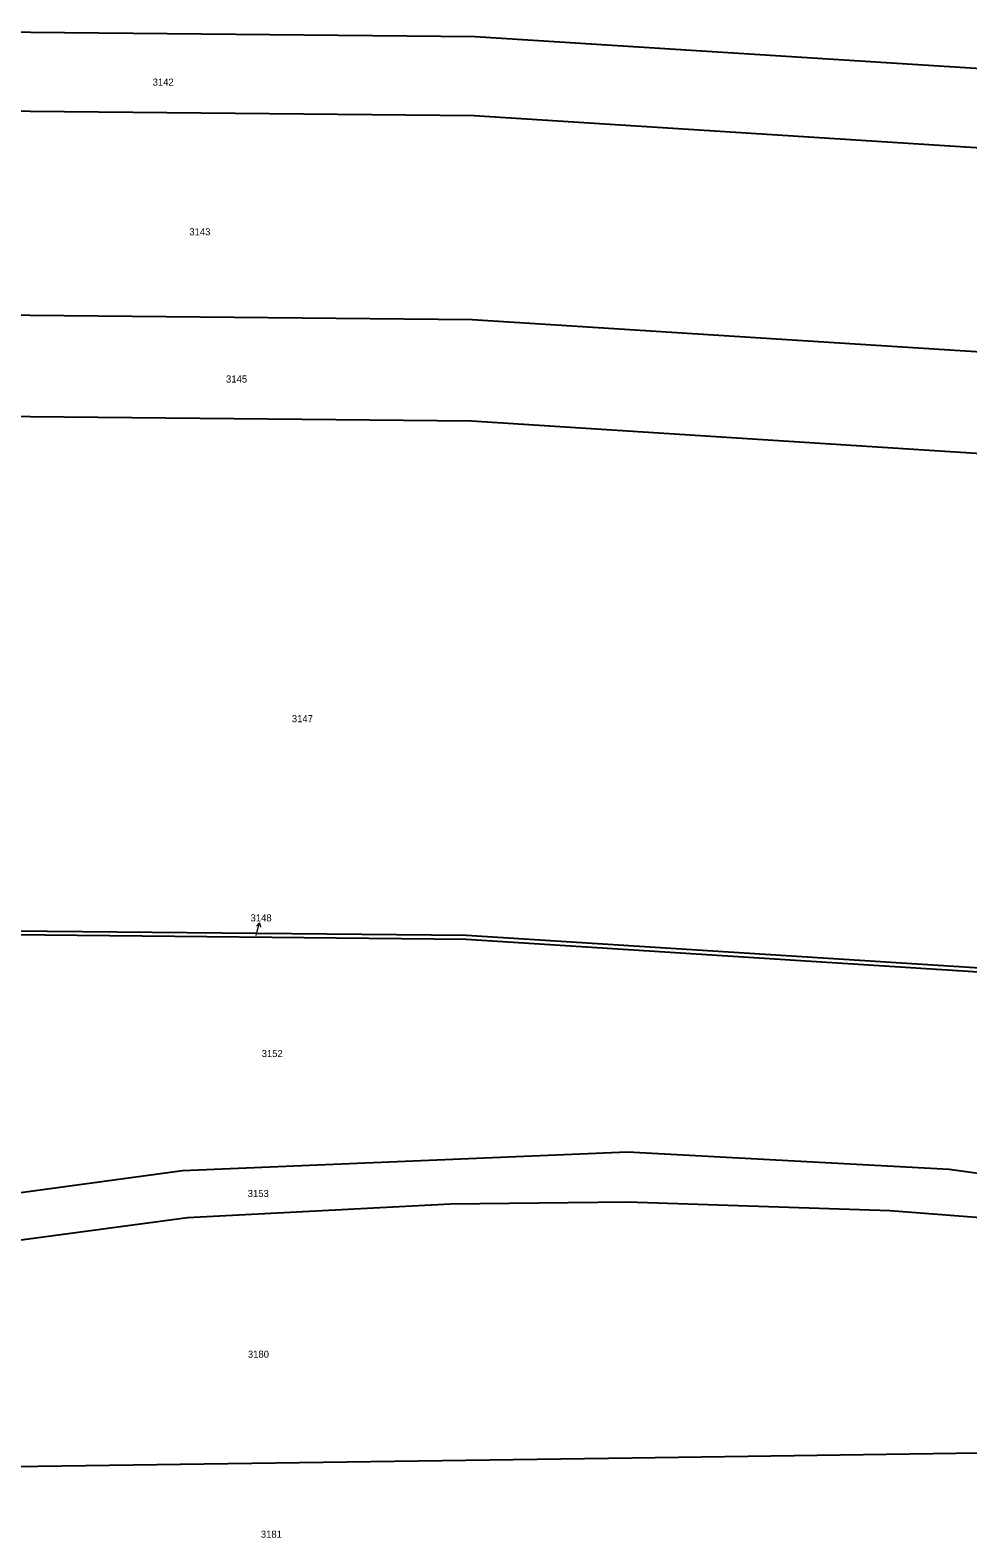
# Model space of a CAD drawing. Extents: x -618848 to -615803, y -1044450 to -1042254.
# Drawn here: x -616481.6 to -616256.9, y -1043034.5 to -1042673.4 of the extents above; entities that cross this region are included whole.
import ezdxf
from ezdxf.enums import TextEntityAlignment as Align

# ---------------------------------------------------------------- set-up
doc = ezdxf.new("R2010")
doc.units = 0
doc.header["$LTSCALE"] = 0.68
doc.layers.add('1', color=7, linetype='Continuous', lineweight=25)
doc.layers.add('7', color=7, linetype='Continuous', lineweight=13)
doc.layers.add('2', color=7, linetype='Continuous')

msp = doc.modelspace()

# ---------------------------------------------------------------- linework, layer by layer
at = {"layer": '1'}
for p, q in [((-616375.02, -1042674.92), (-616536.74, -1042673.36)), ((-616231.12, -1042684.09), (-616375.02, -1042674.92)), ((-616536.19, -1042692.24), (-616375.23, -1042693.79)), ((-616375.23, -1042693.79), (-616191.24, -1042705.51)), ((-616375.73, -1042742.75), (-616534.74, -1042741.2)), ((-616194.35, -1042754.28), (-616375.73, -1042742.75)), ((-616533.99, -1042765.4), (-616375.91, -1042766.94)), ((-616375.91, -1042766.94), (-616204.28, -1042777.88)), ((-616485.9, -1042889.06), (-616377.11, -1042890.12)), ((-616377.12, -1042891.14), (-616485.84, -1042890.08)), ((-616377.11, -1042890.12), (-616250.23, -1042898.2)), ((-616250.63, -1042899.2), (-616377.12, -1042891.14)), ((-616445.14, -1042946.46), (-616338.49, -1042942.01)), ((-616338.49, -1042942.01), (-616261.43, -1042946.19)), ((-616491.65, -1042952.78), (-616445.14, -1042946.46)), ((-616261.43, -1042946.19), (-616232.54, -1042950.22)), ((-616443.96, -1042957.79), (-616380.92, -1042954.49)), ((-616380.92, -1042954.49), (-616338.54, -1042954.02)), ((-616338.54, -1042954.02), (-616275.67, -1042956.05)), ((-616489.83, -1042963.88), (-616443.96, -1042957.79)), ((-616275.67, -1042956.05), (-616245.06, -1042958.45)), ((-616337.34, -1043015.38), (-616485.46, -1043017.48)), ((-616189.22, -1043013.27), (-616337.34, -1043015.38))]:
    msp.add_line(p, q, dxfattribs=at)
at = {"layer": '7'}
msp.add_line((-616426.673, -1042887.141), (-616427.416, -1042887.979), dxfattribs=at)
msp.add_lwpolyline([(-616427.49, -1042890.17), (-616427.45, -1042890.04), (-616426.673, -1042887.141), (-616426.449, -1042888.238)], dxfattribs=at)

# ---------------------------------------------------------------- texts
at = {"layer": '2'}
for s, p in [('3142', (-616452.28, -1042686.655)), ('3143', (-616443.49, -1042722.505)), ('3145', (-616434.7, -1042757.765)), ('3147', (-616418.92, -1042839.115)), ('3152', (-616426.16, -1042919.325)), ('3153', (-616429.5, -1042952.855)), ('3180', (-616429.46, -1042991.345)), ('3181', (-616426.35, -1043034.455))]:
    msp.add_text(s, height=1.7, dxfattribs=at).set_placement(p)
msp.add_text('3148', height=1.7, dxfattribs=at).set_placement((-616426.29, -1042886.835), align=Align.CENTER)

doc.saveas('drawing.dxf')
